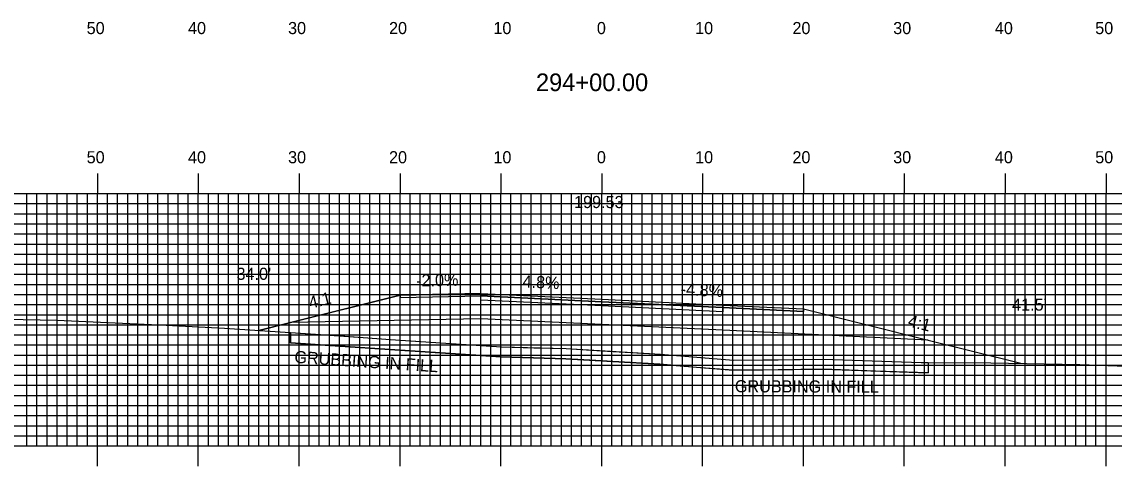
# Model space of a CAD drawing. Extents: x 1814128 to 1814471, y 442591 to 442811.
# Drawn here: x 1814236.5 to 1814344.8, y 442696.7 to 442740.7 of the extents above; entities that cross this region are included whole.
import ezdxf

# ---------------------------------------------------------------- set-up
doc = ezdxf.new("R2010")
doc.units = 0
for name, color, linetype in [('ANNOTATION', 7, 'Continuous'), ('D_Roadway_Centerline', 7, 'Continuous'), ('D_Roadway_Centerline_Text', 7, 'Continuous'), ('D_Roadway_Edge_Shoulder', 7, 'Continuous'), ('D_Roadway_Edge_TW', 7, 'Continuous'), ('D_Roadway_Pavement', 7, 'Continuous'), ('D_Roadway_SlopeLines', 7, 'Continuous'), ('D_Roadway_SubGrade', 7, 'Continuous'), ('D_Text_Standard', 7, 'Continuous'), ('GRUBBING IN FILL', 7, 'Continuous'), ('H_V ANNOTATION', 7, 'Continuous'), ('MAJOR', 7, 'Continuous'), ('MINOR', 7, 'Continuous'), ('S_Roadway_Centerline', 7, 'Continuous')]:
    doc.layers.add(name, color=color, linetype=linetype)

msp = doc.modelspace()

# ---------------------------------------------------------------- linework, layer by layer
at = {"layer": 'D_Roadway_Centerline'}
msp.add_lwpolyline([(1814259.98, 442710.11), (1814263.12, 442710.9), (1814273.99, 442713.61), (1814281.99, 442713.77), (1814293.99, 442713.2), (1814305.99, 442712.62), (1814313.99, 442712.24), (1814326.37, 442709.14), (1814335.53, 442706.85)], dxfattribs=at)
at = {"layer": 'D_Roadway_Edge_Shoulder'}
for points in [[(1814281.99, 442713.77), (1814273.99, 442713.61), (1814273.99, 442713.36), (1814281.99, 442713.52)], [(1814305.99, 442712.62), (1814313.99, 442712.24), (1814313.99, 442711.99), (1814305.99, 442712.37)]]:
    msp.add_lwpolyline(points, close=True, dxfattribs=at)
at = {"layer": 'D_Roadway_Edge_TW'}
msp.add_lwpolyline([(1814281.99, 442713.52), (1814281.99, 442713.77), (1814293.99, 442713.2), (1814305.99, 442712.62), (1814305.99, 442712.37), (1814293.99, 442712.95)], close=True, dxfattribs=at)
at = {"layer": 'D_Roadway_Pavement'}
msp.add_lwpolyline([(1814281.99, 442713.11), (1814281.99, 442713.52), (1814293.99, 442712.95), (1814305.99, 442712.37), (1814305.99, 442711.95), (1814293.99, 442712.53)], close=True, dxfattribs=at)
at = {"layer": 'D_Roadway_SlopeLines'}
for points in [[(1814273.99, 442713.61), (1814259.98, 442710.11)], [(1814313.99, 442712.24), (1814326.37, 442709.14), (1814335.53, 442706.85)]]:
    msp.add_lwpolyline(points, dxfattribs=at)
at = {"layer": 'D_Roadway_SubGrade'}
msp.add_lwpolyline([(1814281.99, 442711.27), (1814263.12, 442710.9), (1814273.99, 442713.61), (1814273.99, 442713.36), (1814281.99, 442713.52), (1814293.99, 442712.95), (1814305.99, 442712.37), (1814313.99, 442711.99), (1814313.99, 442712.24), (1814326.37, 442709.14), (1814305.99, 442710.12), (1814293.99, 442710.7)], close=True, dxfattribs=at)
at = {"layer": 'GRUBBING IN FILL'}
for p, q in [((1814263.12, 442709.89), (1814263.12, 442708.89)), ((1814263.12, 442709.89), (1814263.12, 442708.89)), ((1814326.37, 442706.93), (1814326.37, 442705.91)), ((1814326.37, 442706.93), (1814326.37, 442705.91))]:
    msp.add_line(p, q, dxfattribs=at)
for points in [[(1814263.12, 442709.89), (1814270.34, 442709.4), (1814273.04, 442709.22), (1814278.54, 442708.85), (1814284.04, 442708.49), (1814287.26, 442708.4), (1814290.48, 442708.31), (1814293.99, 442708.1), (1814293.99, 442707.1), (1814290.43, 442707.31), (1814287.21, 442707.4), (1814283.99, 442707.49), (1814278.49, 442707.85), (1814272.98, 442708.22), (1814268.05, 442708.55), (1814263.12, 442708.89)], [(1814263.12, 442709.89), (1814270.34, 442709.4), (1814273.04, 442709.22), (1814278.54, 442708.85), (1814284.04, 442708.49), (1814287.26, 442708.4), (1814290.48, 442708.31), (1814293.99, 442708.1), (1814293.99, 442707.1), (1814290.43, 442707.31), (1814287.21, 442707.4), (1814283.99, 442707.49), (1814278.49, 442707.85), (1814272.98, 442708.22), (1814268.05, 442708.55), (1814263.12, 442708.89)], [(1814293.99, 442708.1), (1814295.14, 442708.03), (1814299.81, 442707.74), (1814303.43, 442707.45), (1814307.05, 442707.16), (1814311.49, 442707.21), (1814315.94, 442707.26), (1814320.8, 442707.09), (1814325.66, 442706.93), (1814326.37, 442706.93), (1814326.37, 442705.91), (1814321.15, 442706.08), (1814315.93, 442706.26), (1814311.47, 442706.21), (1814307.01, 442706.16), (1814303.38, 442706.45), (1814299.74, 442706.75), (1814295.09, 442707.03), (1814293.99, 442707.1)], [(1814293.99, 442708.1), (1814295.14, 442708.03), (1814299.81, 442707.74), (1814303.43, 442707.45), (1814307.05, 442707.16), (1814311.49, 442707.21), (1814315.94, 442707.26), (1814320.8, 442707.09), (1814325.66, 442706.93), (1814326.37, 442706.93), (1814326.37, 442705.91), (1814321.15, 442706.08), (1814315.93, 442706.26), (1814311.47, 442706.21), (1814307.01, 442706.16), (1814303.38, 442706.45), (1814299.74, 442706.75), (1814295.09, 442707.03), (1814293.99, 442707.1)]]:
    msp.add_lwpolyline(points, close=True, dxfattribs=at)
msp.add_lwpolyline([(1814263.12, 442708.89), (1814272.98, 442708.22), (1814283.99, 442707.49), (1814290.43, 442707.31), (1814299.74, 442706.75), (1814307.01, 442706.16), (1814315.93, 442706.26), (1814326.37, 442705.91)], dxfattribs=at)
msp.add_lwpolyline([(1814263.12, 442708.89), (1814272.98, 442708.22), (1814283.99, 442707.49), (1814290.43, 442707.31), (1814299.74, 442706.75), (1814307.01, 442706.16), (1814315.93, 442706.26), (1814326.37, 442705.91)], dxfattribs=at)
at = {"layer": 'MAJOR'}
for p, q in [((1814243.99, 442725.67), (1814243.99, 442723.67)), ((1814253.99, 442725.67), (1814253.99, 442723.67)), ((1814263.99, 442725.67), (1814263.99, 442723.67)), ((1814273.99, 442725.67), (1814273.99, 442723.67)), ((1814283.99, 442725.67), (1814283.99, 442723.67)), ((1814293.99, 442725.67), (1814293.99, 442723.67)), ((1814303.99, 442725.67), (1814303.99, 442723.67)), ((1814313.99, 442725.67), (1814313.99, 442723.67)), ((1814323.99, 442725.67), (1814323.99, 442723.67)), ((1814333.99, 442725.67), (1814333.99, 442723.67)), ((1814343.99, 442725.67), (1814343.99, 442723.67)), ((1814153.99, 442723.67), (1814433.99, 442723.67)), ((1814153.99, 442723.67), (1814433.99, 442723.67)), ((1814243.99, 442698.67), (1814243.99, 442723.67)), ((1814253.99, 442698.67), (1814253.99, 442723.67)), ((1814263.99, 442698.67), (1814263.99, 442723.67)), ((1814273.99, 442698.67), (1814273.99, 442723.67)), ((1814283.99, 442698.67), (1814283.99, 442723.67)), ((1814293.99, 442698.67), (1814293.99, 442723.67)), ((1814303.99, 442698.67), (1814303.99, 442723.67)), ((1814313.99, 442698.67), (1814313.99, 442723.67)), ((1814323.99, 442698.67), (1814323.99, 442723.67)), ((1814333.99, 442698.67), (1814333.99, 442723.67)), ((1814343.99, 442698.67), (1814343.99, 442723.67)), ((1814153.99, 442718.67), (1814433.99, 442718.67)), ((1814153.99, 442713.67), (1814433.99, 442713.67)), ((1814153.99, 442708.67), (1814433.99, 442708.67)), ((1814153.99, 442703.67), (1814433.99, 442703.67)), ((1814153.99, 442698.67), (1814433.99, 442698.67)), ((1814153.99, 442698.67), (1814433.99, 442698.67)), ((1814243.99, 442696.66), (1814243.99, 442698.67)), ((1814253.99, 442696.66), (1814253.99, 442698.67)), ((1814263.99, 442696.66), (1814263.99, 442698.67)), ((1814273.99, 442696.66), (1814273.99, 442698.67)), ((1814283.99, 442696.66), (1814283.99, 442698.67)), ((1814293.99, 442696.66), (1814293.99, 442698.67)), ((1814303.99, 442696.66), (1814303.99, 442698.67)), ((1814313.99, 442696.66), (1814313.99, 442698.67)), ((1814323.99, 442696.66), (1814323.99, 442698.67)), ((1814333.99, 442696.66), (1814333.99, 442698.67)), ((1814343.99, 442696.66), (1814343.99, 442698.67))]:
    msp.add_line(p, q, dxfattribs=at)
at = {"layer": 'MINOR'}
for p, q in [((1814236.99, 442698.67), (1814236.99, 442723.67)), ((1814237.99, 442698.67), (1814237.99, 442723.67)), ((1814238.99, 442698.67), (1814238.99, 442723.67)), ((1814239.99, 442698.67), (1814239.99, 442723.67)), ((1814240.99, 442698.67), (1814240.99, 442723.67)), ((1814241.99, 442698.67), (1814241.99, 442723.67)), ((1814242.99, 442698.67), (1814242.99, 442723.67)), ((1814244.99, 442698.67), (1814244.99, 442723.67)), ((1814245.99, 442698.67), (1814245.99, 442723.67)), ((1814246.99, 442698.67), (1814246.99, 442723.67)), ((1814247.99, 442698.67), (1814247.99, 442723.67)), ((1814248.99, 442698.67), (1814248.99, 442723.67)), ((1814249.99, 442698.67), (1814249.99, 442723.67)), ((1814250.99, 442698.67), (1814250.99, 442723.67)), ((1814251.99, 442698.67), (1814251.99, 442723.67)), ((1814252.99, 442698.67), (1814252.99, 442723.67)), ((1814254.99, 442698.67), (1814254.99, 442723.67)), ((1814255.99, 442698.67), (1814255.99, 442723.67)), ((1814256.99, 442698.67), (1814256.99, 442723.67)), ((1814257.99, 442698.67), (1814257.99, 442723.67)), ((1814258.99, 442698.67), (1814258.99, 442723.67)), ((1814259.99, 442698.67), (1814259.99, 442723.67)), ((1814260.99, 442698.67), (1814260.99, 442723.67)), ((1814261.99, 442698.67), (1814261.99, 442723.67)), ((1814262.99, 442698.67), (1814262.99, 442723.67)), ((1814264.99, 442698.67), (1814264.99, 442723.67)), ((1814265.99, 442698.67), (1814265.99, 442723.67)), ((1814266.99, 442698.67), (1814266.99, 442723.67)), ((1814267.99, 442698.67), (1814267.99, 442723.67)), ((1814268.99, 442698.67), (1814268.99, 442723.67)), ((1814269.99, 442698.67), (1814269.99, 442723.67)), ((1814270.99, 442698.67), (1814270.99, 442723.67)), ((1814271.99, 442698.67), (1814271.99, 442723.67)), ((1814272.99, 442698.67), (1814272.99, 442723.67)), ((1814274.99, 442698.67), (1814274.99, 442723.67)), ((1814275.99, 442698.67), (1814275.99, 442723.67)), ((1814276.99, 442698.67), (1814276.99, 442723.67)), ((1814277.99, 442698.67), (1814277.99, 442723.67)), ((1814278.99, 442698.67), (1814278.99, 442723.67)), ((1814279.99, 442698.67), (1814279.99, 442723.67)), ((1814280.99, 442698.67), (1814280.99, 442723.67)), ((1814281.99, 442698.67), (1814281.99, 442723.67)), ((1814282.99, 442698.67), (1814282.99, 442723.67)), ((1814284.99, 442698.67), (1814284.99, 442723.67)), ((1814285.99, 442698.67), (1814285.99, 442723.67)), ((1814286.99, 442698.67), (1814286.99, 442723.67)), ((1814287.99, 442698.67), (1814287.99, 442723.67)), ((1814288.99, 442698.67), (1814288.99, 442723.67)), ((1814289.99, 442698.67), (1814289.99, 442723.67)), ((1814290.99, 442698.67), (1814290.99, 442723.67)), ((1814291.99, 442698.67), (1814291.99, 442723.67)), ((1814292.99, 442698.67), (1814292.99, 442723.67)), ((1814294.99, 442698.67), (1814294.99, 442723.67)), ((1814295.99, 442698.67), (1814295.99, 442723.67)), ((1814296.99, 442698.67), (1814296.99, 442723.67)), ((1814297.99, 442698.67), (1814297.99, 442723.67)), ((1814298.99, 442698.67), (1814298.99, 442723.67)), ((1814299.99, 442698.67), (1814299.99, 442723.67)), ((1814300.99, 442698.67), (1814300.99, 442723.67)), ((1814301.99, 442698.67), (1814301.99, 442723.67)), ((1814302.99, 442698.67), (1814302.99, 442723.67)), ((1814304.99, 442698.67), (1814304.99, 442723.67)), ((1814305.99, 442698.67), (1814305.99, 442723.67)), ((1814306.99, 442698.67), (1814306.99, 442723.67)), ((1814307.99, 442698.67), (1814307.99, 442723.67)), ((1814308.99, 442698.67), (1814308.99, 442723.67)), ((1814309.99, 442698.67), (1814309.99, 442723.67)), ((1814310.99, 442698.67), (1814310.99, 442723.67)), ((1814311.99, 442698.67), (1814311.99, 442723.67)), ((1814312.99, 442698.67), (1814312.99, 442723.67)), ((1814314.99, 442698.67), (1814314.99, 442723.67)), ((1814315.99, 442698.67), (1814315.99, 442723.67)), ((1814316.99, 442698.67), (1814316.99, 442723.67)), ((1814317.99, 442698.67), (1814317.99, 442723.67)), ((1814318.99, 442698.67), (1814318.99, 442723.67)), ((1814319.99, 442698.67), (1814319.99, 442723.67)), ((1814320.99, 442698.67), (1814320.99, 442723.67)), ((1814321.99, 442698.67), (1814321.99, 442723.67)), ((1814322.99, 442698.67), (1814322.99, 442723.67)), ((1814324.99, 442698.67), (1814324.99, 442723.67)), ((1814325.99, 442698.67), (1814325.99, 442723.67)), ((1814326.99, 442698.67), (1814326.99, 442723.67)), ((1814327.99, 442698.67), (1814327.99, 442723.67)), ((1814328.99, 442698.67), (1814328.99, 442723.67)), ((1814329.99, 442698.67), (1814329.99, 442723.67)), ((1814330.99, 442698.67), (1814330.99, 442723.67)), ((1814331.99, 442698.67), (1814331.99, 442723.67)), ((1814332.99, 442698.67), (1814332.99, 442723.67)), ((1814334.99, 442698.67), (1814334.99, 442723.67)), ((1814335.99, 442698.67), (1814335.99, 442723.67)), ((1814336.99, 442698.67), (1814336.99, 442723.67)), ((1814337.99, 442698.67), (1814337.99, 442723.67)), ((1814338.99, 442698.67), (1814338.99, 442723.67)), ((1814339.99, 442698.67), (1814339.99, 442723.67)), ((1814340.99, 442698.67), (1814340.99, 442723.67)), ((1814341.99, 442698.67), (1814341.99, 442723.67)), ((1814342.99, 442698.67), (1814342.99, 442723.67)), ((1814153.99, 442722.67), (1814433.99, 442722.67)), ((1814153.99, 442721.67), (1814433.99, 442721.67)), ((1814153.99, 442720.67), (1814433.99, 442720.67)), ((1814153.99, 442719.67), (1814433.99, 442719.67)), ((1814153.99, 442717.67), (1814433.99, 442717.67)), ((1814153.99, 442716.67), (1814433.99, 442716.67)), ((1814153.99, 442715.67), (1814433.99, 442715.67)), ((1814153.99, 442714.67), (1814433.99, 442714.67)), ((1814153.99, 442712.67), (1814433.99, 442712.67)), ((1814153.99, 442711.67), (1814433.99, 442711.67)), ((1814153.99, 442710.67), (1814433.99, 442710.67)), ((1814153.99, 442709.67), (1814433.99, 442709.67)), ((1814153.99, 442707.67), (1814433.99, 442707.67)), ((1814153.99, 442706.67), (1814433.99, 442706.67)), ((1814153.99, 442705.67), (1814433.99, 442705.67)), ((1814153.99, 442704.67), (1814433.99, 442704.67)), ((1814153.99, 442702.67), (1814433.99, 442702.67)), ((1814153.99, 442701.67), (1814433.99, 442701.67)), ((1814153.99, 442700.67), (1814433.99, 442700.67)), ((1814153.99, 442699.67), (1814433.99, 442699.67))]:
    msp.add_line(p, q, dxfattribs=at)
at = {"layer": 'S_Roadway_Centerline'}
msp.add_lwpolyline([(1814234.98, 442711.24), (1814239.96, 442711.14), (1814250.79, 442710.62), (1814256.6, 442710.34), (1814267.63, 442709.59), (1814273.04, 442709.22), (1814284.04, 442708.49), (1814290.48, 442708.31), (1814299.81, 442707.74), (1814307.05, 442707.16), (1814315.94, 442707.26), (1814325.66, 442706.93), (1814332.57, 442706.91), (1814341.4, 442706.74), (1814348.79, 442706.48)], dxfattribs=at)

# ---------------------------------------------------------------- texts
at = {"layer": 'ANNOTATION'}
for s, rotation, p in [('-2.0%', 1.1458, (1814275.6, 442714.45)), ('4.8%', 357.2519, (1814286.12, 442714.38)), ('-4.8%', 357.2519, (1814301.8, 442713.62)), ('4:1', 14.0362, (1814265.1, 442712.25)), ('4:1', 345.9638, (1814324.27, 442710.53))]:
    msp.add_text(s, height=1.2, rotation=rotation, dxfattribs=at).set_placement(p)
at = {"layer": 'D_Roadway_Centerline'}
for s, p in [('C', (1814293.99, 442713.2)), ('L', (1814293.99, 442713.19))]:
    msp.add_text(s, height=0.0146, dxfattribs=at).set_placement(p)
at = {"layer": 'D_Roadway_Centerline_Text'}
msp.add_text('199.53', height=1.2, dxfattribs=at).set_placement((1814291.25, 442722.23))
at = {"layer": 'D_Text_Standard'}
for s, p in [("34.0'", (1814257.78, 442715.12)), ("41.5'", (1814334.68, 442712.07))]:
    msp.add_text(s, height=1.2, dxfattribs=at).set_placement(p)
at = {"layer": 'GRUBBING IN FILL'}
for rotation, p in [(356.2133, (1814263.49, 442706.9)), (359.8053, (1814307.19, 442703.98))]:
    msp.add_text('GRUBBING IN FILL', height=1.2, rotation=rotation, dxfattribs=at).set_placement(p)
at = {"layer": 'H_V ANNOTATION'}
for s, height, p in [('50', 1.2, (1814242.92, 442739.47)), ('40', 1.2, (1814252.97, 442739.47)), ('30', 1.2, (1814262.89, 442739.47)), ('20', 1.2, (1814272.9, 442739.47)), ('10', 1.2, (1814283.25, 442739.47)), ('0', 1.2, (1814293.51, 442739.47)), ('10', 1.2, (1814303.25, 442739.47)), ('20', 1.2, (1814312.9, 442739.47)), ('30', 1.2, (1814322.89, 442739.47)), ('40', 1.2, (1814332.97, 442739.47)), ('50', 1.2, (1814342.92, 442739.47)), ('294+00.00', 1.75, (1814287.47, 442733.82)), ('50', 1.2, (1814242.92, 442726.67)), ('40', 1.2, (1814252.97, 442726.67)), ('30', 1.2, (1814262.89, 442726.67)), ('20', 1.2, (1814272.9, 442726.67)), ('10', 1.2, (1814283.25, 442726.67)), ('0', 1.2, (1814293.51, 442726.67)), ('10', 1.2, (1814303.25, 442726.67)), ('20', 1.2, (1814312.9, 442726.67)), ('30', 1.2, (1814322.89, 442726.67)), ('40', 1.2, (1814332.97, 442726.67)), ('50', 1.2, (1814342.92, 442726.67))]:
    msp.add_text(s, height=height, dxfattribs=at).set_placement(p)

doc.saveas('drawing.dxf')
